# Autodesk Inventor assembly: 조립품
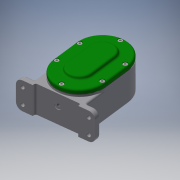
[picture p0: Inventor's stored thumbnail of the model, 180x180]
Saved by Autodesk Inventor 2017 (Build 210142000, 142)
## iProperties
Part Number: 조립품
Material: 일반
Document SubType Name: Assembly
Designer: MRC
Author: MRC
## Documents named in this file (19)
- C:\Users\MRC\Desktop\710609V1010\조립품.iam
- C:\Users\MRC\Desktop\710609V1010\본체.ipt
- C:\Users\MRC\Desktop\710609V1010\개스킷 A.ipt
- C:\Users\MRC\Desktop\710609V1010\개스킷 B.ipt
- C:\Users\MRC\Desktop\710609V1010\베어링 6001.ipt
- 베어링 6001.ipt
- C:\Users\MRC\Desktop\710609V1010\베어링 6002.ipt
- 베어링 6002.ipt
- C:\Users\MRC\Desktop\710609V1010\볼트 M4.ipt
- C:\Users\MRC\Desktop\710609V1010\스퍼기어 A.ipt
- C:\Users\MRC\Desktop\710609V1010\스퍼기어 B.ipt
- C:\Users\MRC\Desktop\710609V1010\오일 실 12 22 7.ipt
- C:\Users\MRC\Desktop\710609V1010\축 A.ipt
- C:\Users\MRC\Desktop\710609V1010\축 B.ipt
- C:\Users\MRC\Desktop\710609V1010\칼라.ipt
- C:\Users\MRC\Desktop\710609V1010\커버 A.ipt
- C:\Users\MRC\Desktop\710609V1010\커버 B.ipt
- C:\Users\MRC\Desktop\710609V1010\키 4 x 4 x 12.ipt
- C:\Users\MRC\Desktop\710609V1010\키 5 x 5 x 12.ipt
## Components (2 placed, 2 different names)
1. 개스킷 A:1
2. 개스킷 B:1
